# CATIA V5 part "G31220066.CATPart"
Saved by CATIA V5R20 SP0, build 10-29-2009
Part number: G31220066
Revision: 10
Definition: design
Nomenclature: G31220066
Source: made
Description: NOT SPECIFIED
Bounding box of the stored display mesh (mm): x -8 to 66, y -15.5 to 15.5, z -15.5 to 15.5
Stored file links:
  C:\Users\Raffaele\Desktop\3D X SITO CF\BOLEX\23-BUSH REF 312\G31220066.CATPart

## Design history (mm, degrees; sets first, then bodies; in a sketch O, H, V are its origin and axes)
Body1 "MANIFOLD_SOLID_BREP #17123" (main body)
  Solid1: solid without history
Body2 "MANIFOLD_SOLID_BREP #17270"
  Solid2: solid without history
Body3 "MANIFOLD_SOLID_BREP #17417"
  Solid3: solid without history
Body4 "MANIFOLD_SOLID_BREP #17564"
  Solid4: solid without history
Body5 "MANIFOLD_SOLID_BREP #17711"
  Solid5: solid without history
Body6 "MANIFOLD_SOLID_BREP #17860"
  Solid6: solid without history
Body7 "MANIFOLD_SOLID_BREP #18009"
  Solid7: solid without history
Body8 "MANIFOLD_SOLID_BREP #18158"
  Solid8: solid without history
Body9 "MANIFOLD_SOLID_BREP #18307"
  Solid9: solid without history
Body10 "MANIFOLD_SOLID_BREP #18456"
  Solid10: solid without history
Body11 "MANIFOLD_SOLID_BREP #18605"
  Solid11: solid without history
Body12 "MANIFOLD_SOLID_BREP #18754"
  Solid12: solid without history
Body13 "MANIFOLD_SOLID_BREP #18903"
  Solid13: solid without history
Body14 "MANIFOLD_SOLID_BREP #19052"
  Solid14: solid without history
Body15 "MANIFOLD_SOLID_BREP #19201"
  Solid15: solid without history
Body16 "MANIFOLD_SOLID_BREP #19350"
  Solid16: solid without history
Body17 "MANIFOLD_SOLID_BREP #19499"
  Solid17: solid without history
Body18 "MANIFOLD_SOLID_BREP #19648"
  Solid18: solid without history
Body19 "MANIFOLD_SOLID_BREP #19797"
  Solid19: solid without history
Body20 "MANIFOLD_SOLID_BREP #19946"
  Solid20: solid without history
Body21 "MANIFOLD_SOLID_BREP #20095"
  Solid21: solid without history
Body22 "MANIFOLD_SOLID_BREP #20244"
  Solid22: solid without history
Body23 "MANIFOLD_SOLID_BREP #20393"
  Solid23: solid without history
Body24 "MANIFOLD_SOLID_BREP #20542"
  Solid24: solid without history
Body25 "MANIFOLD_SOLID_BREP #20691"
  Solid25: solid without history
Body26 "MANIFOLD_SOLID_BREP #20840"
  Solid26: solid without history
Body27 "MANIFOLD_SOLID_BREP #20989"
  Solid27: solid without history
Body28 "MANIFOLD_SOLID_BREP #21138"
  Solid28: solid without history
Body29 "MANIFOLD_SOLID_BREP #21287"
  Solid29: solid without history
Body30 "MANIFOLD_SOLID_BREP #21436"
  Solid30: solid without history
Body31 "MANIFOLD_SOLID_BREP #21585"
  Solid31: solid without history
Body32 "MANIFOLD_SOLID_BREP #21732"
  Solid32: solid without history
Body33 "MANIFOLD_SOLID_BREP #21879"
  Solid33: solid without history
Body34 "MANIFOLD_SOLID_BREP #22028"
  Solid34: solid without history
Body35 "MANIFOLD_SOLID_BREP #22177"
  Solid35: solid without history
Body36 "MANIFOLD_SOLID_BREP #22326"
  Solid36: solid without history
Body37 "MANIFOLD_SOLID_BREP #22475"
  Solid37: solid without history
Body38 "MANIFOLD_SOLID_BREP #22624"
  Solid38: solid without history
Body39 "MANIFOLD_SOLID_BREP #22773"
  Solid39: solid without history
Body40 "MANIFOLD_SOLID_BREP #22922"
  Solid40: solid without history
Body41 "MANIFOLD_SOLID_BREP #23071"
  Solid41: solid without history
Body42 "MANIFOLD_SOLID_BREP #23220"
  Solid42: solid without history
Body43 "MANIFOLD_SOLID_BREP #23369"
  Solid43: solid without history
Body44 "MANIFOLD_SOLID_BREP #23518"
  Solid44: solid without history
Body45 "MANIFOLD_SOLID_BREP #23667"
  Solid45: solid without history
Body46 "MANIFOLD_SOLID_BREP #23816"
  Solid46: solid without history
Body47 "MANIFOLD_SOLID_BREP #23965"
  Solid47: solid without history
Body48 "MANIFOLD_SOLID_BREP #24114"
  Solid48: solid without history
Body49 "MANIFOLD_SOLID_BREP #24263"
  Solid49: solid without history
Body50 "MANIFOLD_SOLID_BREP #24412"
  Solid50: solid without history
Body51 "MANIFOLD_SOLID_BREP #24561"
  Solid51: solid without history
Body52 "MANIFOLD_SOLID_BREP #24710"
  Solid52: solid without history
Body53 "MANIFOLD_SOLID_BREP #24859"
  Solid53: solid without history
Body54 "MANIFOLD_SOLID_BREP #25008"
  Solid54: solid without history
Body55 "MANIFOLD_SOLID_BREP #25157"
  Solid55: solid without history
Body56 "MANIFOLD_SOLID_BREP #25304"
  Solid56: solid without history
Body57 "MANIFOLD_SOLID_BREP #25451"
  Solid57: solid without history
Body58 "MANIFOLD_SOLID_BREP #25600"
  Solid58: solid without history
Body59 "MANIFOLD_SOLID_BREP #25749"
  Solid59: solid without history
Body60 "MANIFOLD_SOLID_BREP #25898"
  Solid60: solid without history
Body61 "MANIFOLD_SOLID_BREP #26047"
  Solid61: solid without history
Body62 "MANIFOLD_SOLID_BREP #26196"
  Solid62: solid without history
Body63 "MANIFOLD_SOLID_BREP #26345"
  Solid63: solid without history
Body64 "MANIFOLD_SOLID_BREP #26492"
  Solid64: solid without history
Body65 "MANIFOLD_SOLID_BREP #26639"
  Solid65: solid without history
Body66 "MANIFOLD_SOLID_BREP #26788"
  Solid66: solid without history
Body67 "MANIFOLD_SOLID_BREP #26937"
  Solid67: solid without history
Body68 "MANIFOLD_SOLID_BREP #27086"
  Solid68: solid without history
Body69 "MANIFOLD_SOLID_BREP #27235"
  Solid69: solid without history
Body70 "MANIFOLD_SOLID_BREP #27384"
  Solid70: solid without history
Body71 "MANIFOLD_SOLID_BREP #27533"
  Solid71: solid without history
Body72 "MANIFOLD_SOLID_BREP #27682"
  Solid72: solid without history
Body73 "MANIFOLD_SOLID_BREP #27831"
  Solid73: solid without history
Body74 "MANIFOLD_SOLID_BREP #27980"
  Solid74: solid without history
Body75 "MANIFOLD_SOLID_BREP #28129"
  Solid75: solid without history
Body76 "MANIFOLD_SOLID_BREP #28278"
  Solid76: solid without history
Body77 "MANIFOLD_SOLID_BREP #28427"
  Solid77: solid without history
Body78 "MANIFOLD_SOLID_BREP #28576"
  Solid78: solid without history
Body79 "MANIFOLD_SOLID_BREP #28725"
  Solid79: solid without history
Body80 "MANIFOLD_SOLID_BREP #28874"
  Solid80: solid without history
Body81 "MANIFOLD_SOLID_BREP #29023"
  Solid81: solid without history
Body82 "MANIFOLD_SOLID_BREP #29172"
  Solid82: solid without history
Body83 "MANIFOLD_SOLID_BREP #29321"
  Solid83: solid without history
Body84 "MANIFOLD_SOLID_BREP #29470"
  Solid84: solid without history
Body85 "MANIFOLD_SOLID_BREP #29619"
  Solid85: solid without history
Body86 "MANIFOLD_SOLID_BREP #29766"
  Solid86: solid without history
Body87 "MANIFOLD_SOLID_BREP #29913"
  Solid87: solid without history
Body88 "MANIFOLD_SOLID_BREP #30060"
  Solid88: solid without history
Body89 "MANIFOLD_SOLID_BREP #30207"
  Solid89: solid without history
Body90 "MANIFOLD_SOLID_BREP #30356"
  Solid90: solid without history
Body91 "MANIFOLD_SOLID_BREP #30505"
  Solid91: solid without history
Body92 "MANIFOLD_SOLID_BREP #30654"
  Solid92: solid without history
Body93 "MANIFOLD_SOLID_BREP #30803"
  Solid93: solid without history
Body94 "MANIFOLD_SOLID_BREP #30952"
  Solid94: solid without history
Body95 "MANIFOLD_SOLID_BREP #31101"
  Solid95: solid without history
Body96 "MANIFOLD_SOLID_BREP #31250"
  Solid96: solid without history
Body97 "MANIFOLD_SOLID_BREP #31399"
  Solid97: solid without history
Body98 "MANIFOLD_SOLID_BREP #31548"
  Solid98: solid without history
Body99 "MANIFOLD_SOLID_BREP #31697"
  Solid99: solid without history
Body100 "MANIFOLD_SOLID_BREP #31846"
  Solid100: solid without history
Body101 "MANIFOLD_SOLID_BREP #31995"
  Solid101: solid without history
Body102 "MANIFOLD_SOLID_BREP #32144"
  Solid102: solid without history
Body103 "MANIFOLD_SOLID_BREP #32293"
  Solid103: solid without history
Body104 "MANIFOLD_SOLID_BREP #32442"
  Solid104: solid without history
Body105 "MANIFOLD_SOLID_BREP #32591"
  Solid105: solid without history
Body106 "MANIFOLD_SOLID_BREP #32740"
  Solid106: solid without history
Body107 "MANIFOLD_SOLID_BREP #32889"
  Solid107: solid without history
Body108 "MANIFOLD_SOLID_BREP #33038"
  Solid108: solid without history
Body109 "MANIFOLD_SOLID_BREP #33187"
  Solid109: solid without history
Body110 "MANIFOLD_SOLID_BREP #33336"
  Solid110: solid without history
Body111 "MANIFOLD_SOLID_BREP #33485"
  Solid111: solid without history
Body112 "MANIFOLD_SOLID_BREP #33632"
  Solid112: solid without history
Body113 "MANIFOLD_SOLID_BREP #33779"
  Solid113: solid without history
Body114 "MANIFOLD_SOLID_BREP #33928"
  Solid114: solid without history
Body115 "MANIFOLD_SOLID_BREP #34077"
  Solid115: solid without history
Body116 "MANIFOLD_SOLID_BREP #34226"
  Solid116: solid without history
Body117 "MANIFOLD_SOLID_BREP #34375"
  Solid117: solid without history
Body118 "MANIFOLD_SOLID_BREP #34524"
  Solid118: solid without history
Body119 "MANIFOLD_SOLID_BREP #34673"
  Solid119: solid without history
Body120 "MANIFOLD_SOLID_BREP #34822"
  Solid120: solid without history
Body121 "MANIFOLD_SOLID_BREP #34971"
  Solid121: solid without history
